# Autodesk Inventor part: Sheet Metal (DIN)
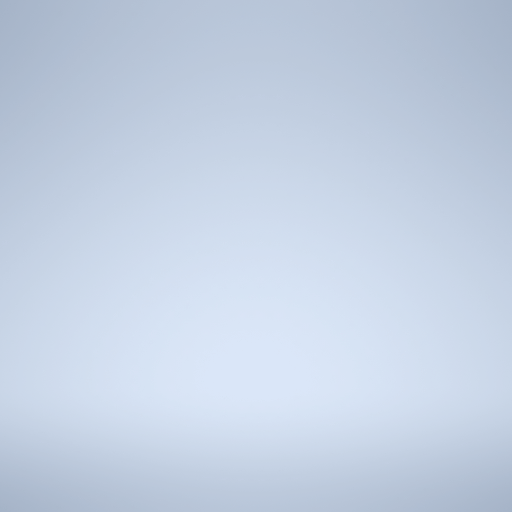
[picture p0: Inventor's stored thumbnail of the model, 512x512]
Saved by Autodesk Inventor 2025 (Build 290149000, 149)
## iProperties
Created: 2024-02
Part Number: Sheet Metal (DIN)
Material: Všeobecné
Document SubType Name: Sheet Metal
Density: 1 g/cm^3
Sheet Metal Rule: Výchozí_mm
Appearance: Výchozí
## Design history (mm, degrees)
other parameters: "Tloušťka" = 0.5, "PoloměrOhybu" = 0.5 (= Tloušťka), "ŠířkaVýštipu" = 0.5 (= Tloušťka), "HloubkaVýštipu" = 0.25 (= 0.5 x Tloušťka), "VelikostRohovéhoVýštipu" = 2 (= 4 x Tloušťka), "SeamGap" = 0.01, "MinimálníZbytek" = 1 (= 2 x Tloušťka), "PřechodovýPoloměr" = 0.5 (= PoloměrOhybu), "VelikostJacobihoPoloměru" = 0.5 (= PoloměrOhybu), "VelikostMezery" = 0.5 (= Tloušťka)
